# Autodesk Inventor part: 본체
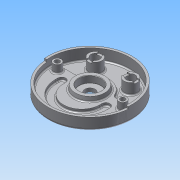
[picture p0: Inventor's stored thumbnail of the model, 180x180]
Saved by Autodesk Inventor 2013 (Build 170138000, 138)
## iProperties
Created: 2015-04
Part Number: 본체
Material: 알루미늄 6061
Document SubType Name: Modeling
Designer: Administrator
Density: 2.71 g/cm^3
Mass: 1053.1 g
Surface Area: 1027.64 cm^2
Volume: 388.598 cm^3
Author: Administrator
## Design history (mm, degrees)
sketch "스케치1"
  geometry: C1 r 95 at (0, 0); 1 further point
  constraints: 1 centre point, 1 coincident
  dimensions: "d5" = 190 diameter of C1
extrude "돌출1" new body sketch "스케치1" distance "d7" = 32; taper "d8" = 0 deg
hole "구멍1" diameter "d11" = 180; stored, may be unused: countersink angle "d15" = 90 deg, drill point angle "d17" = 0 deg; dims "d9" = 10, "d10" = 10, "d12" = 6, "d13" = 4, "d14" = 2, "d16" = 18
sketch "스케치6"
  geometry: C1 r 9 at (-74, 0); C2 r 9 at (74, 0); A1 r 90 centre (0, 0) between (90, 0) and (90, 0) reference; A2 r 74 centre (0, 0) between (-74, 0) and (74, 0)
  constraints: 3 centre point, 2 point on circle, 1 coincident
  dimensions: "d56" = 148 diameter of A2; "d57" = 18 diameter of C1; "d58" = 18 diameter of C2
extrude "돌출5" join sketch "스케치6" distance "d59" = 18; taper "d60" = 0 deg
sketch "스케치8"
  geometry: L1 (-76.916, 12)-(-47.117, 12); L2 (47.117, 12)-(76.916, 12); C1 r 90 at (0, 0) reference; A1 r 42 centre (0, 0) between (38.056, 17.769) and (-38.056, 17.769); A2 r 90 centre (0, 0) between (86.53, 24.75) and (-86.53, 24.75); A3 r 10 centre (-76.916, 22) between (-86.53, 24.75) and (-76.916, 12); A4 r 10 centre (-47.117, 22) between (-47.117, 12) and (-38.056, 17.769); A5 r 10 centre (47.117, 22) between (38.056, 17.769) and (47.117, 12); A6 r 10 centre (76.916, 22) between (76.916, 12) and (86.53, 24.75); 4 further points
  constraints: 16 point on circle, 8 tangent, 6 centre point, 4 end point, 4 equal radius, 4 point on line, 2 coincident, 2 horizontal
  dimensions: "d86" = 84 diameter of A1; "d87" = 12 distance from line of C1.centre L1; "d88" = 12 distance from line of L2 C1.centre; "d89" = 10 radius of A3
extrude "돌출7" cut sketch "스케치8" distance "d90" = 7; taper "d91" = 0 deg
sketch "스케치9"
  geometry: L1 (42, 14)-(17.769, 14) reference; L2 (24.75, 14)-(-90, 14) reference; L3 (0, 0)-(0, 24); L4 (0, 24)-(33.237, 24); L5 (33.237, 24)-(35, 14); L6 (35, 14)-(0, 14)
  constraints: 8 end point, 3 point on line, 2 perpendicular
  dimensions: "d92" = 100 deg angle of L1 L5; "d93" = 70 diameter of L5.end L3; "d95" = 10 distance between parallel lines of L1 L4
revolve "회전2" sketch "스케치9" stored, may be unused: angle "d96" = 90 deg
hole "구멍5" diameter "d99" = 23; stored, may be unused: countersink angle "d103" = 90 deg, drill point angle "d105" = 0 deg; dims "d97" = 10, "d98" = 10, "d100" = 6, "d101" = 50, "d102" = 15, "d104" = 18
sketch "스케치10"
  geometry: L1 (76.916, 12)-(47.117, 12) reference; L2 (-106.837, 52)-(100.665, 52); C1 r 15 at (-40, 52); C2 r 15 at (40, 52); A1 r 42 centre (0, 0) between (38.056, 17.769) and (-38.056, 17.769) reference; A2 r 40 centre (0, 52) between (-40, 52) and (40, 52)
  constraints: 3 centre point, 3 point on line, 2 end point, 2 point on circle, 1 parallel
  dimensions: "d106" = 52 distance from line of A1.centre L2; "d107" = 80 diameter of A2; "d108" = 30 diameter of C1; "d109" = 30 diameter of C2
extrude "돌출8" join sketch "스케치10" distance "d110" = 25; taper "d111" = 0 deg
hole "구멍6" diameter "d120" = 20; stored, may be unused: countersink angle "d124" = 90 deg, drill point angle "d126" = 0 deg; dims "d118" = 10, "d119" = 10, "d121" = 6, "d122" = 50, "d123" = 15, "d125" = 18
hole "구멍7" diameter "d129" = 20; stored, may be unused: countersink angle "d133" = 90 deg, drill point angle "d135" = 0 deg; dims "d127" = 10, "d128" = 10, "d130" = 6, "d131" = 50, "d132" = 15, "d134" = 18
sketch "스케치13"
  geometry: L1 (0, 0)-(0, -74) reference; L2 (36.062, -36.062)-(52.326, -52.326); L3 (-36.062, -36.062)-(-52.326, -52.326); C1 r 95 at (0, 0) reference; A1 r 51 centre (0, 0) between (-36.062, -36.062) and (36.062, -36.062); A2 r 74 centre (0, 0) between (-52.326, -52.326) and (52.326, -52.326)
  constraints: 6 end point, 5 point on circle, 2 centre point, 2 coincident, 1 vertical
  dimensions: "d138" = 102 diameter of A1 (derived)
extrude "돌출9" join sketch "스케치13" distance "d142" = 5.5; taper "d143" = 0 deg
fillet "모깎기1" dims "d144" = 5
fillet "모깎기2" dims "d145" = 5
fillet "모깎기3" dims "d146" = 5
fillet "모깎기5" dims "d159" = 0.3
fillet "모깎기6" dims "d204" = 5
chamfer "모따기1" distance "d161" = 1; stored, may be unused: second distance "d162" = 2, angle "d163" = 45 deg
chamfer "모따기2" distance "d164" = 1; stored, may be unused: second distance "d165" = 2, angle "d166" = 45 deg
fillet "모깎기7" dims "d167" = 3
sketch "스케치16"
  geometry: L1 (0, 0)-(-95, 0); L2 (0, 0)-(95, 0); L3 (-85.36, -7.468)-(-94.638, -8.28); L4 (85.36, -7.468)-(94.638, -8.28); A1 r 95 centre (0, 0) between (94.638, -8.28) and (-94.638, -8.28) reference; A2 r 95 centre (0, 0) between (-94.638, -8.28) and (94.638, -8.28); A3 r 85.686 centre (0, 0) between (-85.36, -7.468) and (85.36, -7.468)
  constraints: 8 end point, 6 point on circle, 2 centre point, 2 coincident, 1 collinear, 1 concentric, 1 horizontal
  dimensions: "d168" = 5 deg angle of L4 L2; "d169" = 5 deg angle of L3 L1
extrude "돌출12" cut sketch "스케치16" distance "d170" = 5; taper "d171" = 0 deg
sketch "스케치17"
  geometry: C1 r 9 at (-74, 0) reference; C2 r 9 at (74, 0) reference; 2 further points
  constraints: 2 coincident
hole "구멍8" sketch "스케치17" at (-74, 0), (74, 0) diameter "d172" = 11; stored, may be unused: countersink angle "d176" = 90 deg, drill point angle "d178" = 0 deg; dims "d173" = 6, "d174" = 18, "d175" = 11, "d177" = 18
sketch "스케치18"
  geometry: L1 (0, -56)-(0, -69); C1 r 68 at (0, 0); A1 r 69 centre (0, 0) between (-45.127, -52.198) and (45.127, -52.198) reference; A2 r 56 centre (0, 0) between (-35.904, -42.975) and (35.904, -42.975) reference; 1 further point
  constraints: 2 end point, 2 point on circle, 1 centre point, 1 coincident, 1 midpoint, 1 other
  dimensions: "d179" = 136 diameter of C1
feature "엠보싱1" sketch "스케치18" dims "d8" = 0, "d86" = 84, "d180" = 0.5, "d181" = 0
sketch "스케치19"
  geometry: L1 (-6, 20.634)-(6, 20.634); L2 (6, 20.634)-(6, -19.694); L3 (6, -19.694)-(-6, -19.694); L4 (-6, -19.694)-(-6, 20.634); L5 (56.541, 6)-(100.942, 6); L6 (100.942, 6)-(100.942, -6); L7 (100.942, -6)-(56.541, -6); L8 (56.541, -6)-(56.541, 6); C1 r 10 at (0, 0) reference; C2 r 15 at (80, 0) reference; C3 r 10 at (80, 0) reference; 1 further point
  constraints: 16 end point, 4 parallel, 2 horizontal, 2 perpendicular
  dimensions: "d182" = 6 distance from line of L2 C1.centre; "d183" = 12 distance between parallel lines of L4 L2; "d186" = 6 distance from line of L5 C2.centre; "d187" = 12 distance between parallel lines of L7 L5
extrude "돌출13" cut sketch "스케치19" distance "d188" = 3; taper "d189" = 0 deg
sketch "스케치20"
  geometry: L1 (-47.117, 12)-(-74, 12) reference; L2 (-74, 12)-(-76.916, 12) reference; L3 (-104.875, -19)-(111.353, -19); L4 (-104.875, -14)-(111.353, -14); L5 (-41, -14)-(-41, -19); L6 (41, -14)-(41, -19); L7 (59, -14)-(59, -19) reference; L8 (-50, -8.649)-(-50, -28.3); L9 (50, -13.23)-(50, -23.111); L10 (-59, -14)-(-59, -19); A1 r 42 centre (0, 0) between (38.056, 17.769) and (-38.056, 17.769) reference; A2 r 37.517 centre (0, 0) between (-37.446, -2.304) and (37.446, -2.304) reference; A3 r 9 centre (50, -14) between (59, -14) and (41, -14); A4 r 9 centre (-50, -14) between (-41, -14) and (-59, -14); A5 r 59 centre (0, -19) between (-59, -19) and (59, -19); A6 r 59 centre (0, -19) between (58.788, -14) and (-50.2, 12); A7 r 41 centre (0, -19) between (-41, -19) and (41, -19); A8 r 41 centre (0, -19) between (37.446, -2.304) and (-37.446, -2.304)
  constraints: 16 end point, 14 point on circle, 11 point on line, 7 parallel, 6 centre point, 2 vertical, 1 coincident, 1 perpendicular
  dimensions: "d190" = 19 distance from line of L3 A1.centre; "d191" = 5 distance between parallel lines of L4 L3; "d195" = 18 diameter of A3; "d196" = 18 diameter of A4; "d198" = 9 distance between parallel lines of L6 L9
extrude "돌출14" cut sketch "스케치20" distance "d200" = 7; taper "d201" = 0 deg
fillet "모깎기8" dims "d202" = 3
fillet "모깎기9" dims "d203" = 3
fillet "모깎기10" dims "d205" = 3
node "솔리드1"
other parameters: "d30" = 118, "d31" = 82, "d85" = 12, "d136" = 148, "d140" = 45 deg, "d141" = 90 deg, "d192" = 118, "d194" = 82, "d197" = 9
